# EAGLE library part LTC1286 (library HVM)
12-BIT ADC DIFF INPUT
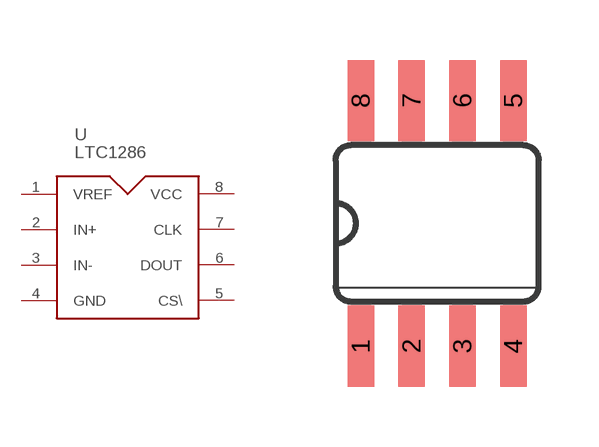
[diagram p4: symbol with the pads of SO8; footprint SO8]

Designator prefix U

## LTC1286  [SO8]
1  VREF  pas
2  IN+  pas
3  IN-  pas
4  GND  pas
5  CS\  pas
6  DOUT  pas
7  CLK  pas
8  VCC  pas

## Footprint SO8 (pad centres in mm)
SO8 PACKAGE
smd 0.66 x 2.032: 1 -1.905,-3.073; 2 -0.635,-3.073; 3 0.635,-3.073; 4 1.905,-3.073; 5 1.905,3.073; 6 0.635,3.073; 7 -0.635,3.073; 8 -1.905,3.073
